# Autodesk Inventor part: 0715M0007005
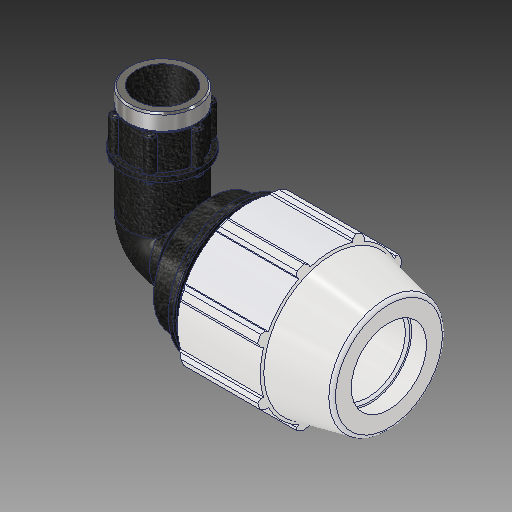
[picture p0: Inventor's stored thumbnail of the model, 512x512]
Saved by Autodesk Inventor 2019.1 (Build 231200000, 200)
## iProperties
Created: 2017-02
Part Number: 0715M0007005
Material: PVC-Piping
Description: PLASSON 90° ELBOW FEMALE ADAPTOR 3/4'' - 1/2''F
Document SubType Name: Modeling
Designer: KIM
Mass: 92.6774 g
Surface Area: 199.44 cm^2
Volume: 66.1981 cm^3
Density: 1.4 g/cm^3
Appearance: PTFE
Author: KIM
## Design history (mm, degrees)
derived "0715M0.ipt"
feature "Solid1::0715M0.ipt"
tag "TaggingFeature1"
body "Solid1"
other parameters: "d2" = 26.6, "d4" = 6.6675, "d5" = 20.0025, "d7" = 54.102, "d9" = 11.43, "d11" = 2.667, "d13" = 120 deg, "d14" = 39.9, "d15" = 12 deg, "d16" = 47.06874, "d18" = 1.33, "d19" = 35 deg, "d20" = 17.5 deg, "d21" = 50.31486, "d23" = 0, "d25" = 360 deg, "d27" = 1.08204, "d33" = 0.532, "d42" = 29.6037, "d43" = 1.62306, "d46" = 0.798, "d51" = 80.01, "d68" = 2.667, "d72" = 45.974, "d73" = 24.2203, "d74" = 18.034, "d75" = 27.85335, "d76" = 18.631, "d77" = 19.8374, "d79" = 7.4524, "d80" = 0.55893, "d83" = 0, "d84" = 0, "d91" = 40.5765, "d93" = 56.896, "d94" = 18.631, "d95" = 13.0417, "d96" = 8.001, "d97" = 50 deg, "d98" = 16.7679, "d99" = 0.5, "d100" = 0.5, "d101" = 6.01133, "d102" = 24.2203, "d103" = 15.3289, "d104" = 0, "d108" = 360 deg, "d110" = 0.72661, "d_" = 26.6, "E_" = 54.102, "A_" = 80.01, "l_" = 56.896, "l_2" = 18.034, "A_1" = 45.974, "G_" = 18.631, "d105" = 3.63304
